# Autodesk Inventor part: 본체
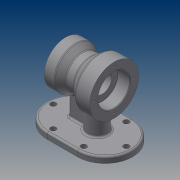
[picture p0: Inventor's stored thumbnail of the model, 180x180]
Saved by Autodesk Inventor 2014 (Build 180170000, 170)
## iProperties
Created: 2020-01
Part Number: 본체
Material: Generic
Document SubType Name: Modeling
Designer: kh
Density: 1 g/cm^3
Appearance: Default
Author: kh
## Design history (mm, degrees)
sketch "Sketch1"
  geometry: L1 (-25, -45)-(25, -45); L2 (25, -45)-(25, 45); L3 (25, 45)-(-25, 45); L4 (-25, 45)-(-25, -45); L5 (-25, -45)-(25, 45); L6 (25, -45)-(-25, 45); A1 r 45 centre (25, 0) between (25, -45) and (25, 45); A2 r 45 centre (-25, 0) between (-25, 45) and (-25, -45); 1 further point
  constraints: 12 end point, 4 midpoint, 4 point on circle, 2 centre point, 2 parallel, 1 horizontal, 1 perpendicular
  dimensions: "d0" = 50 distance of L3.end L2.end; "d1" = 90 distance of L1.end L2.end
extrude "Extrusion1" new body sketch "Sketch1" distance "d2" = 10; taper "d3" = 0 deg
sketch "Sketch2"
  geometry: L1 (25, 45)-(-25, 45) reference; L2 (-25, -45)-(25, -45) reference; L3 (-25, 35)-(25, 35); L4 (25, -35)-(-25, -35); A1 r 45 centre (25, 0) between (25, -45) and (25, 45) reference; A2 r 45 centre (-25, 0) between (-25, 45) and (-25, -45) reference; A3 r 35 centre (25, 0) between (25, -35) and (25, 35); A4 r 35 centre (-25, 0) between (-25, 35) and (-25, -35); 7 further points
  constraints: 6 point on circle, 4 coincident, 4 end point, 2 centre point, 3 other
  dimensions: "d4" = 10 distance between parallel lines of L1 L3
hole "Hole1" sketch "Sketch2" at (-25, 35), (-60, 0), (-25, -35), (25, -35), (60, 0), (25, 35) diameter "d7" = 9; stored, may be unused: countersink angle "d11" = 90 deg, drill point angle "d13" = 0 deg; dims "d8" = 6, "d9" = 4, "d10" = 2, "d12" = 15
workplane "Work Plane5"
sketch "Sketch3"
  geometry: 1 further point
sketch "Sketch4"
  geometry: L1 (-25, 0)-(-70, 0) reference; L2 (25, 0)-(-25, 0) reference; L3 (70, 0)-(25, 0) reference; L4 (-58.776, 80)-(57.127, 80); L5 (-40, 80)-(-40, 120); L6 (-40, 120)-(-16, 120); L7 (-16, 120)-(-1.103, 107.5); L8 (-1.103, 107.5)-(12.207, 107.5); L9 (40, 115)-(40, 80); L10 (-70, 0)-(-70, 10) reference; L11 (12.207, 107.5)-(22.919, 115); L12 (40, 115)-(22.919, 115); 1 further point
  constraints: 16 end point, 4 perpendicular, 2 parallel, 2 point on line
  dimensions: "d17" = 80 distance between parallel lines of L1 L4; "d18" = 80 diameter of L6 L4; "d19" = 24 distance of L5.end L6.end; "d20" = 40 deg angle of L8 L7; "d22" = 30 distance between parallel lines of L5 L10; "d23" = 80 distance between parallel lines of L9 L5; "d24" = 55 diameter of L8 L4; "d29" = 35 deg angle of L11 L8; "d30" = 70 diameter of L12 L4
revolve "Revolution1" sketch "Sketch4" stored, may be unused: angle "d31" = 90 deg
sketch "Sketch5"
  geometry: L1 (-3.199, 5)-(-30, 5); L2 (-30, 5)-(-30, -5); L3 (-30, -5)-(-3.199, -5); L4 (17.714, 5)-(-30, -5); L5 (-30, 5)-(17.714, -5); A1 r 45 centre (25, 0) between (25, -45) and (25, 45) reference; A2 r 16.37 centre (12, 0) between (-4.366, 0.373) and (-4.366, -0.373); A3 r 16 centre (12, 0) between (-3.199, -5) and (-3.199, 5); 6 further points
  constraints: 10 end point, 5 midpoint, 5 point on circle, 3 horizontal alignment, 2 centre point, 2 point on line, 1 horizontal, 1 parallel, 1 perpendicular
  dimensions: "d33" = 58 distance of A2.centre point (70, 0); "d34" = 10 distance of L1.end L2.end; "d35" = 100 distance from line of L2 point (70, 0); "d37" = 16 radius of A3
extrude "Extrusion2" join sketch "Sketch5" distance "d38" = 79.75; taper "d39" = 0 deg
hole "Hole2" diameter "d42" = 52; stored, may be unused: countersink angle "d46" = 90 deg, drill point angle "d48" = 0 deg; dims "d40" = 10, "d41" = 10, "d43" = 6, "d44" = 4, "d45" = 2, "d47" = 20
hole "Hole3" diameter "d51" = 32; stored, may be unused: countersink angle "d55" = 90 deg, drill point angle "d57" = 0 deg; dims "d49" = 10, "d50" = 10, "d52" = 6, "d53" = 4, "d54" = 2, "d56" = 100.25
hole "Hole4" diameter "d60" = 40; stored, may be unused: countersink angle "d64" = 90 deg, drill point angle "d66" = 0 deg; dims "d58" = 10, "d59" = 10, "d61" = 6, "d62" = 4, "d63" = 2, "d65" = 17
sketch "Sketch6"
  geometry: C1 r 26 at (0, 0) reference; 2 further points
  dimensions: "d67" = 33 distance of C1.centre point (-33, 0)
hole "Hole5" sketch "Sketch6" at (-33, 0) diameter "d68" = 3.242; stored, may be unused: countersink angle "d72" = 90 deg, drill point angle "d74" = 118 deg; dims "d69" = 9, "d70" = 4, "d71" = 2, "d73" = 11
pattern_circular "Circular Pattern1" dims angle "d76" = 360 deg
sketch "Sketch7"
  geometry: C1 r 20 at (0, 0) reference; 2 further points
  dimensions: "d78" = 27.5 distance of point (27.5, 0) C1.centre
hole "Hole6" sketch "Sketch7" at (27.5, 0) diameter "d79" = 3.242; stored, may be unused: countersink angle "d83" = 90 deg, drill point angle "d85" = 118 deg; dims "d80" = 9, "d81" = 4, "d82" = 2, "d84" = 11
pattern_circular "Circular Pattern2" dims angle "d87" = 360 deg
sketch "Sketch8"
  geometry: L1 (50, 0)-(0, 0) reference; L2 (50, 0)-(50, 0) reference; L3 (50, 0)-(50, -10) reference; L4 (50, -10)-(50, -10) reference; L5 (50, 0)-(50, -10) reference; L6 (95, 0)-(95, -10) reference; L7 (50, -10)-(95, -10) reference; L8 (50, 0)-(95, 0) reference; L9 (-45, 0)-(0, 0) reference; L10 (-45, 0)-(-45, -10) reference; L11 (-45, -10)-(0, -10) reference; 3 further points
  constraints: 1 midpoint, 1 vertical alignment, 1 other
  dimensions: "d89" = 70 distance from line of point (25, -4) L6 (derived); "d90" = 4 distance from line of L1 point (25, -4)
emboss "Emboss1" sketch "Sketch8" dims "d0" = 50, "d1" = 90, "d9" = 4, "d91" = 0.5, "d92" = 0
fillet "Fillet1" dims "d93" = 3
fillet "Fillet2" dims "d94" = 3
fillet "Fillet3" dims "d95" = 3
fillet "Fillet4" dims "d96" = 3
fillet "Fillet5" dims "d97" = 0.3
chamfer "Chamfer1" distance "d98" = 1; stored, may be unused: second distance "d99" = 2, angle "d100" = 45 deg
body "Solid1"
node "Projected Loop1"
other parameters: "d32" = 32
